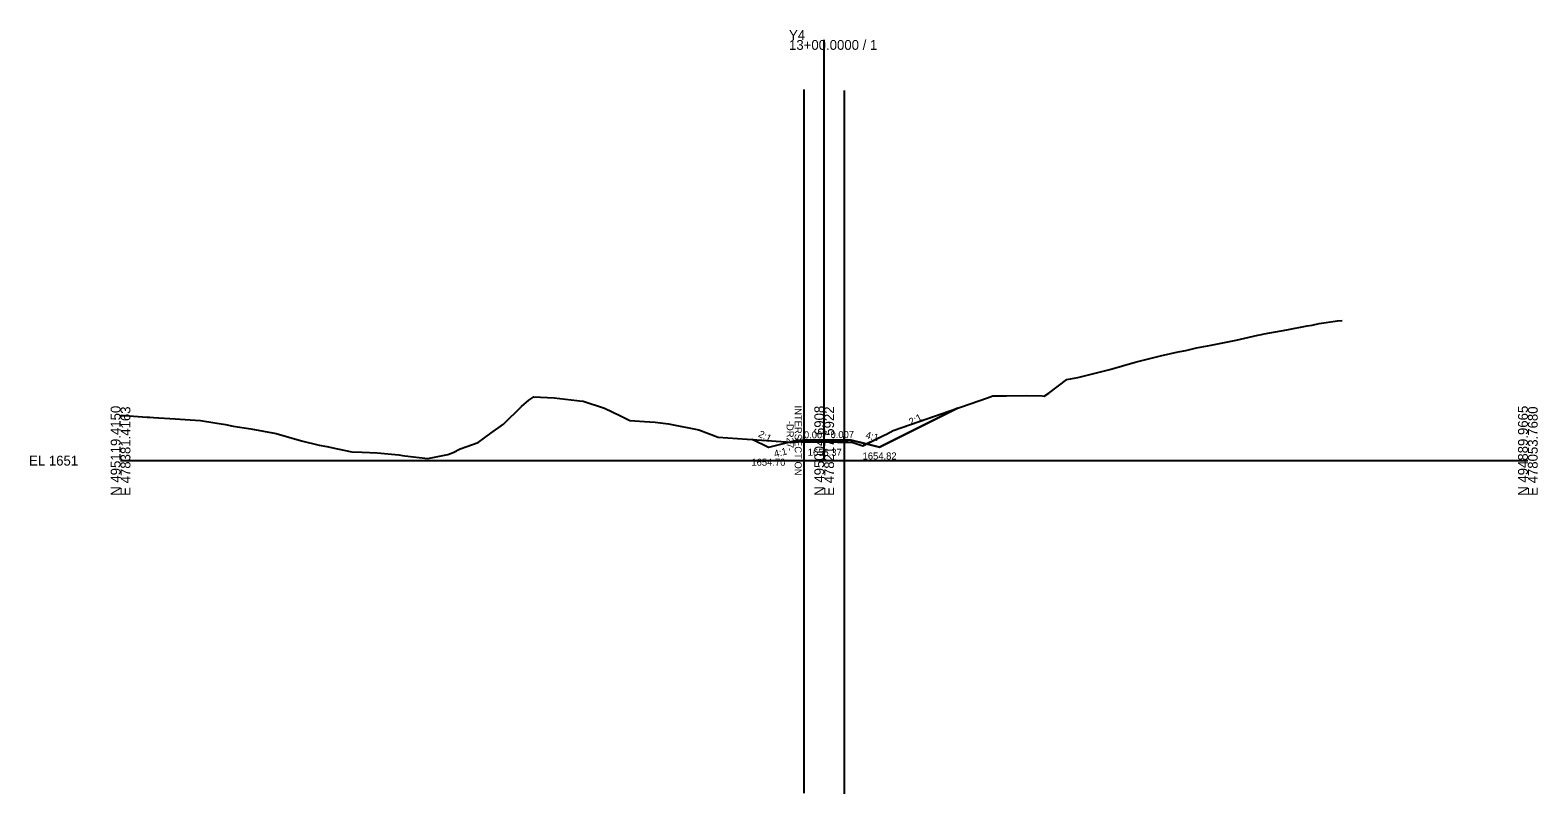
# Model space of a CAD drawing. Extents: x -26 to 403, y -10 to 5108.
# Drawn here: x -25.7 to 402.8, y 2905.3 to 3122.4 of the extents above; entities that cross this region are included whole.
import ezdxf

# ---------------------------------------------------------------- set-up
doc = ezdxf.new("R2010")
doc.units = 0
for name, color, linetype in [('Exist Cross Section Cell', 7, 'Continuous'), ('Exist XS Center Line Elevation Label', 7, 'Continuous'), ('Exist XS Ground Line', 7, 'Continuous'), ('Prop XS Ditch Slope Text', 7, 'Continuous'), ('Prop XS Ditch Standard Text', 7, 'Continuous'), ('Prop XS Dump Level', 7, 'Continuous'), ('Prop XS Earthwork Shape', 7, 'Continuous'), ('Prop XS EOT Tick Mark', 7, 'Continuous'), ('Prop XS Finish Grade', 7, 'Continuous'), ('Prop XS Finish Grade Earthwork', 7, 'Continuous'), ('Prop XS Finish Grade Pavement', 7, 'Continuous'), ('Prop XS Pvmt Edge Slope', 7, 'Continuous'), ('Prop XS SE Text', 7, 'Continuous'), ('Prop XS Shear Point Label', 7, 'Continuous'), ('Prop XS Shoulder Borrow Shape', 7, 'Continuous'), ('Prop XS Side Slope Text', 7, 'Continuous'), ('Prop XS Subgrade Earthwork', 7, 'Continuous'), ('Scratch_Level_0', 7, 'Continuous'), ('Scratch_Level_1', 7, 'Continuous'), ('Scratch_Level_4', 7, 'Continuous')]:
    doc.layers.add(name, color=color, linetype=linetype)

msp = doc.modelspace()

# ---------------------------------------------------------------- linework, layer by layer
at = {"layer": 'Exist Cross Section Cell'}
for p, q in [((200, 3000), (200, 3119.58)), ((0, 3000), (200, 3000)), ((200, 3000), (400, 3000))]:
    msp.add_line(p, q, dxfattribs=at)
at = {"layer": 'Exist XS Ground Line'}
msp.add_lwpolyline([(0, 3012.81), (1.15, 3012.82), (7.58, 3012.36), (8.33, 3012.34), (9.39, 3012.29), (15.51, 3011.84), (19.79, 3011.6), (22.69, 3011.44), (26.83, 3010.74), (29.87, 3010.27), (32, 3009.81), (37.05, 3009.01), (44.26, 3007.7), (51.42, 3005.61), (56.42, 3004.39), (58.6, 3004.03), (61.7, 3003.32), (65.78, 3002.55), (68.63, 3002.4), (72.96, 3002.23), (79.14, 3001.62), (80.14, 3001.5), (80.84, 3001.37), (87.32, 3000.65), (93.05, 3001.72), (94.5, 3002.34), (96.57, 3003.35), (101.69, 3005.17), (105.27, 3007.8), (108.87, 3010.33), (114.01, 3015.39), (116.05, 3017.18), (117.48, 3018.14), (123.23, 3017.82), (129.69, 3017.14), (130.41, 3017.03), (131.45, 3016.86), (137.59, 3014.92), (141.9, 3012.85), (144.77, 3011.45), (148.88, 3011.11), (151.96, 3010.98), (155.78, 3010.45), (164.41, 3008.8), (169.89, 3006.72), (189.09, 3005.36), (190.55, 3005.19), (195.68, 3005.59), (196.4, 3005.49), (197.74, 3005.44), (200, 3005.37), (203.82, 3005.25), (205.64, 3005.28), (207.9, 3005.22), (210.94, 3004.24), (217.01, 3007.21), (217.71, 3007.55), (219.56, 3008.56), (246.37, 3017.86), (247.97, 3018.38), (248.33, 3018.43), (251.82, 3018.44), (257.54, 3018.55), (261.96, 3018.41), (262.55, 3018.33), (263.8, 3019.21), (268.97, 3023.11), (272.08, 3023.6), (281.22, 3025.93), (288.42, 3027.97), (295.59, 3029.79), (300.63, 3030.91), (302.77, 3031.32), (305.81, 3032.03), (309.95, 3032.79), (312.85, 3033.39), (317.13, 3034.22), (323.25, 3035.68), (324.31, 3035.88), (325.06, 3036.02), (331.49, 3037.15), (337.27, 3038.32), (338.67, 3038.53), (340.69, 3038.95), (345.86, 3039.74), (347.2, 3039.86)], dxfattribs=at)
at = {"layer": 'Prop XS Dump Level'}
for q in [(194.17, 3005.84), (205.68, 3005.92)]:
    msp.add_line((200, 3005.88), q, dxfattribs=at)
at = {"layer": 'Prop XS Earthwork Shape'}
for p, q in [((193.62, 3005.29), (194.17, 3005.3)), ((194.17, 3005.3), (200.72, 3005.35)), ((200.72, 3005.35), (200, 3005.37)), ((205.68, 3005.38), (200.72, 3005.35)), ((200.72, 3005.35), (203.82, 3005.25))]:
    msp.add_line(p, q, dxfattribs=at)
for points in [[(211.97, 3004.74), (217.01, 3007.21), (217.71, 3007.55), (219.56, 3008.56), (237.86, 3014.91), (215.68, 3003.82)], [(190.24, 3005.22), (184.17, 3003.7), (179.5, 3006.04), (189.09, 3005.36)], [(189.09, 3005.36), (190.24, 3005.22), (184.17, 3003.7), (179.5, 3006.04)], [(193.49, 3005.42), (193.14, 3005.77), (192.17, 3005.7), (190.24, 3005.22), (190.55, 3005.19)]]:
    msp.add_lwpolyline(points, close=True, dxfattribs=at)
for points in [[(194.17, 3005.47), (193.49, 3005.42), (193.62, 3005.29)], [(200, 3005.37), (197.74, 3005.44), (196.4, 3005.49), (195.68, 3005.59), (194.17, 3005.47)], [(203.82, 3005.25), (205.64, 3005.28), (205.68, 3005.27)], [(205.68, 3005.27), (207.9, 3005.22), (210.94, 3004.24), (211.97, 3004.74), (207.68, 3005.82), (206.7, 3005.87), (206.22, 3005.39), (205.68, 3005.38)]]:
    msp.add_lwpolyline(points, dxfattribs=at)
at = {"layer": 'Prop XS EOT Tick Mark'}
msp.add_line((205.68, 3005.92), (205.68, 3006.92), dxfattribs=at)
at = {"layer": 'Prop XS Finish Grade'}
msp.add_line((205.68, 3005.92), (206.7, 3005.87), dxfattribs=at)
at = {"layer": 'Prop XS Finish Grade Earthwork'}
for p, q in [((215.68, 3003.82), (237.86, 3014.91)), ((206.7, 3005.87), (207.68, 3005.82)), ((207.68, 3005.82), (215.68, 3003.82))]:
    msp.add_line(p, q, dxfattribs=at)
at = {"layer": 'Prop XS Finish Grade Pavement'}
for p, q in [((194.17, 3005.84), (200, 3005.88)), ((200, 3005.88), (205.68, 3005.92))]:
    msp.add_line(p, q, dxfattribs=at)
at = {"layer": 'Prop XS Pvmt Edge Slope'}
msp.add_line((205.68, 3005.92), (206.22, 3005.39), dxfattribs=at)
at = {"layer": 'Prop XS Shear Point Label'}
msp.add_line((194.17, 3015.88), (194.17, 2994.97), dxfattribs=at)
at = {"layer": 'Prop XS Shoulder Borrow Shape'}
msp.add_lwpolyline([(205.68, 3005.92), (206.7, 3005.87), (206.22, 3005.39)], close=True, dxfattribs=at)
at = {"layer": 'Prop XS Subgrade Earthwork'}
for p, q in [((205.68, 3005.38), (194.17, 3005.3)), ((205.68, 3005.38), (206.22, 3005.39)), ((206.22, 3005.39), (206.7, 3005.87))]:
    msp.add_line(p, q, dxfattribs=at)
at = {"layer": 'Scratch_Level_0'}
for p, q in [((184.17, 3003.7), (179.5, 3006.04)), ((184.17, 3003.7), (179.5, 3006.04)), ((192.17, 3005.7), (184.17, 3003.7)), ((190.24, 3005.22), (184.17, 3003.7)), ((192.17, 3005.7), (190.24, 3005.22)), ((193.14, 3005.77), (192.17, 3005.7)), ((194.17, 3005.84), (193.14, 3005.77)), ((193.62, 3005.29), (193.14, 3005.77)), ((194.17, 3005.84), (193.62, 3005.29)), ((194.17, 3005.3), (193.62, 3005.29)), ((194.17, 3005.84), (194.17, 3006.84))]:
    msp.add_line(p, q, dxfattribs=at)
msp.add_lwpolyline([(194.17, 3005.84), (193.14, 3005.77), (193.62, 3005.29)], close=True, dxfattribs=at)
at = {"layer": 'Scratch_Level_1'}
for p, q in [((194.17, 3105.47), (194.17, 2905.47)), ((194.17, 3105.47), (194.17, 2905.47)), ((194.17, 3105.47), (194.17, 2905.47)), ((205.68, 3105.27), (205.68, 2905.27)), ((205.68, 3105.27), (205.68, 2905.27)), ((205.68, 3105.27), (205.68, 2905.27))]:
    msp.add_line(p, q, dxfattribs=at)
at = {"layer": 'Scratch_Level_4'}
msp.add_line((194.17, 3005.47), (205.68, 3005.27), dxfattribs=at)

# ---------------------------------------------------------------- texts
at = {"layer": 'Exist Cross Section Cell'}
for s, p in [('Y4', (190, 3119.58)), ('13+00.0000 / 1', (190, 3116.78)), ('EL 1651', (-26, 2998.6))]:
    msp.add_text(s, height=2.8, dxfattribs=at).set_placement(p)
for s, p in [('N 495119.4150', (0, 2990)), ('E 478381.4163', (2.8, 2990)), ('N 495004.6908', (200, 2990)), ('E 478217.5922', (202.8, 2990)), ('N 494889.9665', (400, 2990)), ('E 478053.7680', (402.8, 2990))]:
    msp.add_text(s, height=2.8, rotation=90, dxfattribs=at).set_placement(p)
at = {"layer": 'Exist XS Center Line Elevation Label'}
msp.add_text('1656.37', height=2, dxfattribs=at).set_placement((195.32, 3001.37))
at = {"layer": 'Prop XS Ditch Slope Text'}
msp.add_text('4:1', height=2, rotation=345.9649, dxfattribs=at).set_placement((211.6, 3006.41))
at = {"layer": 'Prop XS Ditch Standard Text'}
msp.add_text('1654.82', height=2, dxfattribs=at).set_placement((210.91, 3000.32))
at = {"layer": 'Prop XS Dump Level'}
msp.add_text('Case1', height=0.04, dxfattribs=at).set_placement((207.68, 3005.78))
at = {"layer": 'Prop XS SE Text'}
for p in [(194.24, 3006.33), (201.79, 3006.38)]:
    msp.add_text('0.007', height=2, rotation=0.4202, dxfattribs=at).set_placement(p)
at = {"layer": 'Prop XS Shear Point Label'}
for s, p in [('INTERSECTION', (191.61, 3015.66)), ('-DR27-', (189.31, 3011.3))]:
    msp.add_text(s, height=2, rotation=270, dxfattribs=at).set_placement(p)
at = {"layer": 'Prop XS Side Slope Text'}
msp.add_text('2:1', height=2, rotation=26.5632, dxfattribs=at).set_placement((224.68, 3009.99))
at = {"layer": 'Scratch_Level_0'}
for s, rotation, p in [('2:1', 333.4355, (181.08, 3006.92)), ('4:1', 14.0359, (185.98, 3000.91))]:
    msp.add_text(s, height=2, rotation=rotation, dxfattribs=at).set_placement(p)
for s, height, p in [('Case1', 0.04, (192.17, 3005.66)), ('1654.70', 2, (179.31, 2998.55))]:
    msp.add_text(s, height=height, dxfattribs=at).set_placement(p)

doc.saveas('drawing.dxf')
